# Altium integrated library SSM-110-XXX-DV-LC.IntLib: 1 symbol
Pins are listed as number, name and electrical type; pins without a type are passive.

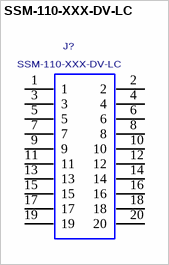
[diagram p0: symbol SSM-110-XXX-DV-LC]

## SSM-110-XXX-DV-LC
designator J?
Socket Strip, Surface Mount, Double Row ,0.100" Pitch, 16 PINS.; MANUFACTURER: SAMTEC
footprint SSM-110-XXX-DV-LC
pins: 1, 2, 3, 4, 5, 6, 7, 8, 9, 10, 11, 12, 13, 14, 15, 16, 17, 18, 19, 20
